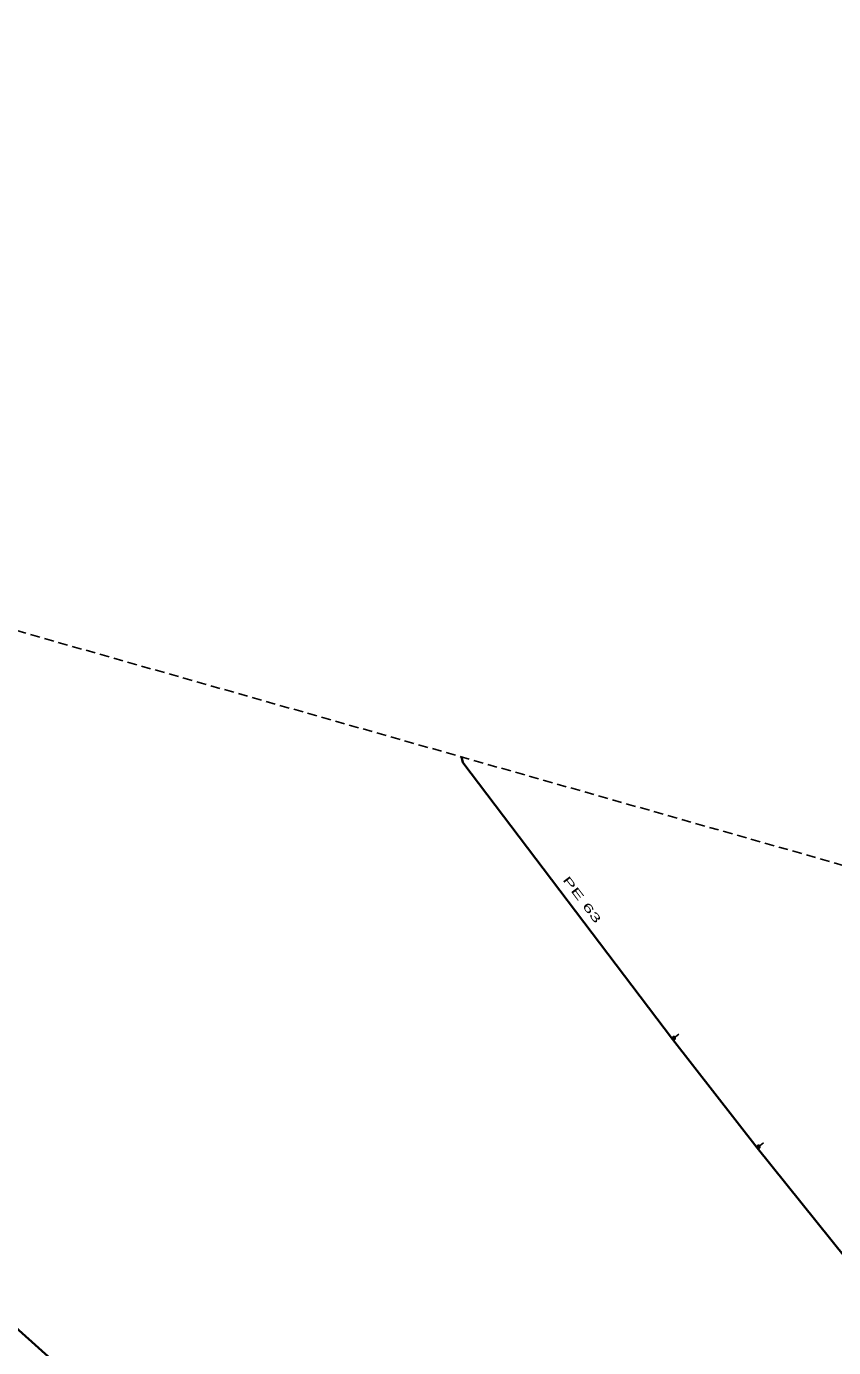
# Model space of a CAD drawing. Extents: x -873619 to -867639, y -1015082 to -1012326.
# Drawn here: x -868203.9 to -868092.9, y -1012689.5 to -1012507.8 of the extents above; entities that cross this region are included whole.
import ezdxf

# ---------------------------------------------------------------- set-up
doc = ezdxf.new("R2010")
doc.units = 0
doc.header["$LTSCALE"] = 0.44
doc.linetypes.add('MEDIUM_DASHED', pattern=[4.5, 3, -1.5])
for name, color, linetype, lineweight in [('1', 7, 'Continuous', 13), ('12', 7, 'Continuous', 13), ('3', 7, 'Continuous', 25), ('62', 7, 'MEDIUM_DASHED', 25)]:
    doc.layers.add(name, color=color, linetype=linetype, lineweight=lineweight)

msp = doc.modelspace()

# ---------------------------------------------------------------- linework, layer by layer
at = {"layer": '1', "lineweight": 35}
for points in [[(-868086.156, -1012682.341), (-868087.143, -1012682.341), (-868103.456, -1012662.024), (-868115.099, -1012647.08), (-868143.914, -1012609.042), (-868144.109, -1012608.264)], [(-868094.808, -1012782.506), (-868128.65, -1012753.034), (-868142.107, -1012741.315), (-868163.447, -1012723.713), (-868165.629, -1012721.604), (-868186.647, -1012703.368), (-868189.69, -1012700.802), (-868224.291, -1012669.746), (-868245.779, -1012651.034), (-868246.236, -1012651.387)]]:
    msp.add_lwpolyline(points, dxfattribs=at)
at = {"layer": '12'}
for points in [[(-868114.669, -1012646.93), (-868114.675, -1012646.878), (-868114.692, -1012646.828), (-868114.721, -1012646.784), (-868114.758, -1012646.747), (-868114.803, -1012646.72), (-868114.853, -1012646.703), (-868114.906, -1012646.699), (-868114.958, -1012646.706), (-868115.007, -1012646.725), (-868115.05, -1012646.754), (-868115.086, -1012646.793), (-868115.112, -1012646.838), (-868115.128, -1012646.889), (-868115.131, -1012646.941), (-868115.123, -1012646.993), (-868115.103, -1012647.042), (-868115.072, -1012647.085), (-868115.033, -1012647.119), (-868114.987, -1012647.145), (-868114.936, -1012647.159), (-868114.883, -1012647.161), (-868114.832, -1012647.151), (-868114.784, -1012647.13), (-868114.741, -1012647.099), (-868114.707, -1012647.058), (-868114.683, -1012647.012), (-868114.671, -1012646.961)], [(-868114.699, -1012646.93), (-868114.705, -1012646.881), (-868114.722, -1012646.835), (-868114.75, -1012646.795), (-868114.787, -1012646.763), (-868114.831, -1012646.741), (-868114.879, -1012646.73), (-868114.928, -1012646.73), (-868114.975, -1012646.743), (-868115.018, -1012646.767), (-868115.054, -1012646.8), (-868115.081, -1012646.841), (-868115.097, -1012646.888), (-868115.101, -1012646.937), (-868115.094, -1012646.985), (-868115.075, -1012647.03), (-868115.045, -1012647.07), (-868115.007, -1012647.101), (-868114.963, -1012647.121), (-868114.915, -1012647.131), (-868114.866, -1012647.129), (-868114.819, -1012647.114), (-868114.776, -1012647.089), (-868114.742, -1012647.055), (-868114.716, -1012647.013), (-868114.702, -1012646.966)], [(-868114.729, -1012646.93), (-868114.735, -1012646.885), (-868114.752, -1012646.843), (-868114.78, -1012646.808), (-868114.816, -1012646.781), (-868114.858, -1012646.764), (-868114.903, -1012646.759), (-868114.948, -1012646.765), (-868114.989, -1012646.784), (-868115.024, -1012646.812), (-868115.051, -1012646.849), (-868115.067, -1012646.891), (-868115.071, -1012646.936), (-868115.064, -1012646.981), (-868115.045, -1012647.022), (-868115.016, -1012647.056), (-868114.979, -1012647.082), (-868114.936, -1012647.098), (-868114.891, -1012647.101), (-868114.846, -1012647.093), (-868114.806, -1012647.073), (-868114.772, -1012647.044), (-868114.746, -1012647.006), (-868114.732, -1012646.963)], [(-868114.759, -1012646.93), (-868114.764, -1012646.889), (-868114.782, -1012646.852), (-868114.809, -1012646.821), (-868114.844, -1012646.8), (-868114.884, -1012646.789), (-868114.925, -1012646.791), (-868114.964, -1012646.804), (-868114.998, -1012646.828), (-868115.023, -1012646.86), (-868115.038, -1012646.898), (-868115.041, -1012646.939), (-868115.033, -1012646.979), (-868115.013, -1012647.015), (-868114.984, -1012647.044), (-868114.947, -1012647.063), (-868114.907, -1012647.071), (-868114.866, -1012647.067), (-868114.828, -1012647.052), (-868114.796, -1012647.026), (-868114.773, -1012646.992), (-868114.76, -1012646.953)], [(-868114.789, -1012646.93), (-868114.794, -1012646.894), (-868114.812, -1012646.862), (-868114.838, -1012646.837), (-868114.872, -1012646.822), (-868114.908, -1012646.819), (-868114.943, -1012646.827), (-868114.974, -1012646.847), (-868114.997, -1012646.875), (-868115.01, -1012646.909), (-868115.01, -1012646.946), (-868114.999, -1012646.981), (-868114.978, -1012647.01), (-868114.948, -1012647.031), (-868114.913, -1012647.041), (-868114.876, -1012647.039), (-868114.842, -1012647.025), (-868114.815, -1012647.002), (-868114.796, -1012646.97), (-868114.789, -1012646.935)], [(-868114.819, -1012646.93), (-868114.824, -1012646.899), (-868114.841, -1012646.873), (-868114.867, -1012646.856), (-868114.897, -1012646.849), (-868114.928, -1012646.853), (-868114.955, -1012646.87), (-868114.973, -1012646.894), (-868114.981, -1012646.925), (-868114.977, -1012646.955), (-868114.962, -1012646.983), (-868114.938, -1012647.002), (-868114.908, -1012647.011), (-868114.877, -1012647.008), (-868114.849, -1012646.994), (-868114.829, -1012646.97), (-868114.819, -1012646.941)], [(-868114.849, -1012646.93), (-868114.854, -1012646.906), (-868114.871, -1012646.888), (-868114.894, -1012646.879), (-868114.918, -1012646.882), (-868114.939, -1012646.896), (-868114.95, -1012646.918), (-868114.95, -1012646.943), (-868114.938, -1012646.964), (-868114.918, -1012646.978), (-868114.893, -1012646.981), (-868114.87, -1012646.972), (-868114.854, -1012646.954)], [(-868114.879, -1012646.93), (-868114.884, -1012646.915), (-868114.899, -1012646.909), (-868114.914, -1012646.913), (-868114.921, -1012646.927), (-868114.917, -1012646.942), (-868114.904, -1012646.951), (-868114.889, -1012646.948), (-868114.879, -1012646.936)], [(-868103.027, -1012661.87), (-868103.034, -1012661.818), (-868103.051, -1012661.768), (-868103.08, -1012661.724), (-868103.117, -1012661.687), (-868103.162, -1012661.66), (-868103.212, -1012661.643), (-868103.265, -1012661.639), (-868103.316, -1012661.646), (-868103.365, -1012661.665), (-868103.409, -1012661.694), (-868103.445, -1012661.733), (-868103.471, -1012661.778), (-868103.487, -1012661.829), (-868103.49, -1012661.881), (-868103.482, -1012661.933), (-868103.462, -1012661.982), (-868103.431, -1012662.025), (-868103.392, -1012662.059), (-868103.346, -1012662.085), (-868103.294, -1012662.099), (-868103.242, -1012662.101), (-868103.191, -1012662.091), (-868103.142, -1012662.07), (-868103.1, -1012662.039), (-868103.066, -1012661.998), (-868103.042, -1012661.952), (-868103.029, -1012661.901)], [(-868103.058, -1012661.87), (-868103.064, -1012661.821), (-868103.081, -1012661.775), (-868103.108, -1012661.735), (-868103.146, -1012661.703), (-868103.19, -1012661.681), (-868103.238, -1012661.67), (-868103.287, -1012661.67), (-868103.333, -1012661.683), (-868103.377, -1012661.707), (-868103.413, -1012661.74), (-868103.44, -1012661.781), (-868103.456, -1012661.828), (-868103.46, -1012661.877), (-868103.453, -1012661.925), (-868103.434, -1012661.97), (-868103.404, -1012662.01), (-868103.365, -1012662.041), (-868103.321, -1012662.061), (-868103.274, -1012662.071), (-868103.225, -1012662.069), (-868103.178, -1012662.054), (-868103.135, -1012662.029), (-868103.1, -1012661.995), (-868103.075, -1012661.953), (-868103.061, -1012661.906)], [(-868103.088, -1012661.87), (-868103.093, -1012661.825), (-868103.11, -1012661.783), (-868103.139, -1012661.748), (-868103.174, -1012661.721), (-868103.217, -1012661.704), (-868103.262, -1012661.699), (-868103.306, -1012661.705), (-868103.348, -1012661.724), (-868103.382, -1012661.752), (-868103.409, -1012661.789), (-868103.426, -1012661.831), (-868103.429, -1012661.876), (-868103.423, -1012661.921), (-868103.404, -1012661.962), (-868103.375, -1012661.996), (-868103.338, -1012662.022), (-868103.294, -1012662.038), (-868103.25, -1012662.041), (-868103.205, -1012662.033), (-868103.164, -1012662.013), (-868103.13, -1012661.984), (-868103.105, -1012661.946), (-868103.091, -1012661.903)], [(-868103.118, -1012661.87), (-868103.122, -1012661.829), (-868103.141, -1012661.792), (-868103.168, -1012661.761), (-868103.203, -1012661.74), (-868103.243, -1012661.729), (-868103.284, -1012661.731), (-868103.323, -1012661.744), (-868103.357, -1012661.768), (-868103.382, -1012661.8), (-868103.397, -1012661.838), (-868103.399, -1012661.879), (-868103.392, -1012661.919), (-868103.372, -1012661.955), (-868103.343, -1012661.984), (-868103.306, -1012662.003), (-868103.266, -1012662.011), (-868103.225, -1012662.007), (-868103.186, -1012661.992), (-868103.154, -1012661.966), (-868103.132, -1012661.932), (-868103.119, -1012661.893)], [(-868103.147, -1012661.87), (-868103.152, -1012661.834), (-868103.171, -1012661.802), (-868103.196, -1012661.777), (-868103.23, -1012661.762), (-868103.267, -1012661.759), (-868103.301, -1012661.767), (-868103.333, -1012661.787), (-868103.355, -1012661.815), (-868103.369, -1012661.849), (-868103.369, -1012661.886), (-868103.358, -1012661.921), (-868103.337, -1012661.95), (-868103.306, -1012661.971), (-868103.272, -1012661.981), (-868103.235, -1012661.979), (-868103.201, -1012661.965), (-868103.174, -1012661.942), (-868103.154, -1012661.91), (-868103.147, -1012661.875)], [(-868103.178, -1012661.87), (-868103.183, -1012661.839), (-868103.2, -1012661.813), (-868103.225, -1012661.796), (-868103.255, -1012661.789), (-868103.287, -1012661.793), (-868103.314, -1012661.81), (-868103.331, -1012661.834), (-868103.34, -1012661.865), (-868103.336, -1012661.895), (-868103.321, -1012661.923), (-868103.296, -1012661.942), (-868103.267, -1012661.951), (-868103.235, -1012661.948), (-868103.208, -1012661.934), (-868103.188, -1012661.91), (-868103.178, -1012661.881)], [(-868103.208, -1012661.87), (-868103.213, -1012661.846), (-868103.23, -1012661.828), (-868103.252, -1012661.819), (-868103.277, -1012661.822), (-868103.298, -1012661.836), (-868103.309, -1012661.858), (-868103.309, -1012661.883), (-868103.296, -1012661.904), (-868103.277, -1012661.918), (-868103.252, -1012661.921), (-868103.228, -1012661.912), (-868103.213, -1012661.894)], [(-868103.238, -1012661.87), (-868103.243, -1012661.855), (-868103.257, -1012661.849), (-868103.272, -1012661.853), (-868103.279, -1012661.867), (-868103.276, -1012661.882), (-868103.262, -1012661.891), (-868103.247, -1012661.888), (-868103.238, -1012661.876)]]:
    msp.add_lwpolyline(points, close=True, dxfattribs=at)
at = {"layer": '3'}
for points in [[(-868115.099, -1012647.08), (-868114.9, -1012646.93), (-868114.184, -1012646.391)], [(-868102.552, -1012661.311), (-868103.259, -1012661.87), (-868103.456, -1012662.024)]]:
    msp.add_lwpolyline(points, dxfattribs=at)
at = {"layer": '62'}
msp.add_lwpolyline([(-873556.163, -1013770.63), (-872990.942, -1013058.87), (-872369.897, -1012591.341), (-871448.796, -1012465.737), (-870583.52, -1012702.99), (-868999.506, -1012326.176), (-868524.999, -1012528.539), (-868252.856, -1012577.385), (-867687.635, -1012737.88), (-867638.789, -1013044.914), (-867827.196, -1013184.475), (-868176.097, -1013763.652), (-868434.285, -1014335.85), (-868650.604, -1014635.906), (-869550.77, -1014963.874), (-870206.706, -1015082.5), (-871092.916, -1015026.676), (-871923.303, -1014566.126), (-872607.15, -1014370.741), (-872865.338, -1014447.499), (-873284.02, -1014259.092), (-873402.646, -1014252.114), (-873618.965, -1014280.026)], close=True, dxfattribs=at)

# ---------------------------------------------------------------- texts
at = {"layer": '1', "width": 1.9}
msp.add_text('PE 63 ', height=1.1, rotation=307, dxfattribs=at).set_placement((-868130.249, -1012625.175))

doc.saveas('drawing.dxf')
